(* Logix 5000 project; controller ZaxisVmpSample 1769-L16ER-BB1B rev 30.11; software revision 30.00 *)

TASK MainTask (continuous, watchdog 500 ms) : MainProgram, VMP_Interface

MODULES
   Local : 1769-L16ER-BB1B (PointIO 0, rev 30.11)
      Pump01 : ETHERNET-MODULE (Ethernet 192.168.1.131, rev 1.1, Output RPI 20 ms)
      Pump02 : ETHERNET-MODULE (Ethernet 192.168.1.132, rev 1.1, Output RPI 20 ms)
      Pump03 : ETHERNET-MODULE (Ethernet 192.168.1.133, rev 1.1, Output RPI 20 ms)
      Pump00 : ETHERNET-MODULE (Ethernet 192.168.1.130, rev 1.1, Output RPI 20 ms)
      Discrete_IO : Embedded (PointIO 1, rev 30.11, Output RPI 20 ms)
           Local:1:I.Data.0   // Green Push Btn
           Local:1:I.Data.1   // Red Push Btn
END_MODULES

TYPE VMP_Cfg :
STRUCT
   ReadyInterlock : BOOL;   // ReadyInterlock
   EthernetRunReady : BOOL;   // EthernetRunReady
   HoldOnFault : BOOL;   // HoldOnFault
   Spare1_3 : BOOL;   // Spare Bit
   Spare1_4 : BOOL;   // Spare Bit
   Spare1_5 : BOOL;   // Spare Bit
   Spare1_6 : BOOL;   // Spare Bit
   Spare1_7 : BOOL;   // Spare Bit
   DecPlaces : SINT;   // DecimalPlaces
   SpareByte1 : SINT;   // Spare data1
   SpareByte2 : SINT;   // Spare data1
END_STRUCT
END_TYPE

TYPE VMP_IN :
STRUCT
   Ready : BOOL;   // Ready to Run
   Running : BOOL;   // Running
   Abort : BOOL;   // Abort State
   Direction : BOOL;   // Direction CCW
   ContinuousRun : BOOL;   // Continuous Run
   MotorRunning : BOOL;   // Motors Running
   AtMaxShot : BOOL;   // AtMaxShot
   CmdAck : BOOL;   // PLC Cmd Ack
   Spare1_8 : BOOL;   // Spare Bit
   Spare1_9 : BOOL;   // Spare Bit
   Spare1_10 : BOOL;   // Spare Bit
   Spare1_11 : BOOL;   // Spare Bit
   Spare1_12 : BOOL;   // Spare Bit
   Spare1_13 : BOOL;   // Spare Bit
   Spare1_14 : BOOL;   // Spare Bit
   Spare1_15 : BOOL;   // Spare Bit
   Spare1_16 : BOOL;   // Spare Bit
   Spare1_17 : BOOL;   // Spare Bit
   Spare1_18 : BOOL;   // Spare Bit
   Spare1_19 : BOOL;   // Spare Bit
   Spare1_20 : BOOL;   // Spare Bit
   Spare1_21 : BOOL;   // Spare Bit
   Spare1_22 : BOOL;   // Spare Bit
   Spare1_23 : BOOL;   // Spare Bit
   Spare1_24 : BOOL;   // Spare Bit
   Spare1_25 : BOOL;   // Spare Bit
   Spare1_26 : BOOL;   // Spare Bit
   Spare1_27 : BOOL;   // Spare Bit
   Spare1_28 : BOOL;   // Spare Bit
   FaultDispenseMotor : BOOL;   // Disp Motor Fault
   FaultAdjustMotor : BOOL;   // Adj Motor Fault
   FaultAdjustSensor : BOOL;   // Adj Sensor Fault
   CurProgram : DINT;   // Program
   CurRevolutions : DINT;   // Revolutions
   CurVolume : REAL;   // Volume
   CurRpm : DINT;   // RPM
   VolumeDint : DINT;   // Vol as Dint
   Spare_In_DInt2 : DINT;   // Spare data2
   FineAdj : INT;   // FineAdj
   Spare_In_Int1 : INT;   // Spare_In_Int 1
END_STRUCT
END_TYPE

TYPE VMP_OUT :
STRUCT
   OkToRun : BOOL;   // Ok to Run
   Start : BOOL;   // Start
   Abort : BOOL;   // Abort Run
   Direction : BOOL;   // Direction CCW
   ContinuousRun : BOOL;   // Run Continuously
   SetMaxShotSize : BOOL;   // Set Max Volumn
   SetShotSize : BOOL;   // Set Volume
   IgnorePLC : BOOL;   // Ignore PLC Cmds
   IncFineAdj : BOOL;   // IncFineAdj
   DecFineAdj : BOOL;   // DecFineAdj
   ResetRevsCnt : BOOL;   // ResetRevsCnt
   Spare11 : BOOL;   // Spare11
   Spare12 : BOOL;   // Spare12
   Spare13 : BOOL;   // Spare13
   Spare14 : BOOL;   // Spare14
   Spare15 : BOOL;   // Spare15
   Spare16 : BOOL;   // Spare16
   Spare17 : BOOL;   // Spare17
   Spare18 : BOOL;   // Spare18
   Spare19 : BOOL;   // Spare19
   Spare20 : BOOL;   // Spare20
   Spare21 : BOOL;   // Spare21
   Spare22 : BOOL;   // Spare22
   Spare23 : BOOL;   // Spare23
   Spare24 : BOOL;   // Spare24
   Spare25 : BOOL;   // Spare25
   Spare26 : BOOL;   // Spare26
   Spare27 : BOOL;   // Spare27
   Spare28 : BOOL;   // Spare28
   Spare29 : BOOL;   // Spare29
   Spare30 : BOOL;   // Spare30
   Spare31 : BOOL;   // Spare31
   Program : DINT;   // Program
   Revolutions : DINT;   // Revolutions
   Volume : REAL;   // Volume
   Rpm : DINT;   // RPM
   Spare_Out_DInt1 : DINT;   // SpareDInt1
   Spare_Out_DInt2 : DINT;   // SpareDInt2
   FineAdjOut : INT;   // FineAdj
   Spare_Out_Int1 : INT;   // Sapre_Out_Int1
END_STRUCT
END_TYPE

TYPE VMP_Prg :
STRUCT
   CalDispenseTime : BOOL;   // CalDispenseTime
   Direction : BOOL;   // Direction CCW
   SetShotSize : BOOL;   // Set Volume
   ContinuousRun : BOOL;   // Run Continuously
   Spare1_4 : BOOL;   // Spare Bit
   Spare1_5 : BOOL;   // Spare Bit
   Spare1_6 : BOOL;   // Spare Bit
   Spare1_7 : BOOL;   // Spare Bit
   Spare1_8 : BOOL;   // Spare Bit
   Spare1_9 : BOOL;   // Spare Bit
   Spare1_10 : BOOL;   // Spare Bit
   Spare1_11 : BOOL;   // Spare Bit
   Spare1_12 : BOOL;   // Spare Bit
   Spare1_13 : BOOL;   // Spare Bit
   Spare1_14 : BOOL;   // Spare Bit
   Spare1_15 : BOOL;   // Spare Bit
   Spare1_16 : BOOL;   // Spare Bit
   Spare1_17 : BOOL;   // Spare Bit
   Spare1_18 : BOOL;   // Spare Bit
   Spare1_19 : BOOL;   // Spare Bit
   Spare1_20 : BOOL;   // Spare Bit
   Spare1_21 : BOOL;   // Spare Bit
   Spare1_22 : BOOL;   // Spare Bit
   Spare1_23 : BOOL;   // Spare Bit
   Spare1_24 : BOOL;   // Spare Bit
   Spare1_25 : BOOL;   // Spare Bit
   Spare1_26 : BOOL;   // Spare Bit
   Spare1_27 : BOOL;   // Spare Bit
   Spare1_28 : BOOL;   // Spare Bit
   Spare1_29 : BOOL;   // Spare Bit
   Spare1_30 : BOOL;   // Spare Bit
   Spare1_31 : BOOL;   // Spare Bit
   Program : DINT;   // Program
   PullBack : DINT;   // PullBack
   InitialRPM : DINT;   // InitialRPM
   RPM : DINT;   // RPM
   FinalRPM : DINT;   // FinalRPM
   FineAdjust : DINT;   // FineAdjust
   Acceleration : DINT;   // Acceleration
   Deceleration : DINT;   // Deceleration
   LoopCycles : DINT;   // LoopCycles
   LinkedProgram : DINT;   // LinkedProgram
   LinkedTimeDelay : DINT;   // LinkedTimeDelay
   MotorCurrent : DINT;   // MotorCurrent
   Revolutions : DINT;   // Revolutions
   AprxDispenseTime : DINT;   // DispenseTime
   Volume : REAL;   // Volume
   ProgramName : STRING;   // ProgramName
END_STRUCT
END_TYPE

TYPE VMP_Setup :
STRUCT
   ReadyInterlock : BOOL;   // RdyInputEnabled
   EthernetRunReady : BOOL;   // EthSendBusy
   HoldOnFault : BOOL;   // HoldOnFault
   Spare1_3 : BOOL;   // Spare Bit
   Spare1_4 : BOOL;   // Spare Bit
   Spare1_5 : BOOL;   // Spare Bit
   Spare1_6 : BOOL;   // Spare Bit
   Spare1_7 : BOOL;   // Spare Bit
   Spare1_8 : BOOL;   // Spare Bit
   Spare1_9 : BOOL;   // Spare Bit
   Spare1_10 : BOOL;   // Spare Bit
   Spare1_11 : BOOL;   // Spare Bit
   Spare1_12 : BOOL;   // Spare Bit
   Spare1_13 : BOOL;   // Spare Bit
   Spare1_14 : BOOL;   // Spare Bit
   Spare1_15 : BOOL;   // Spare Bit
   Spare1_16 : BOOL;   // Spare Bit
   Spare1_17 : BOOL;   // Spare Bit
   Spare1_18 : BOOL;   // Spare Bit
   Spare1_19 : BOOL;   // Spare Bit
   Spare1_20 : BOOL;   // Spare Bit
   Spare1_21 : BOOL;   // Spare Bit
   Spare1_22 : BOOL;   // Spare Bit
   Spare1_23 : BOOL;   // Spare Bit
   Spare1_24 : BOOL;   // Spare Bit
   Spare1_25 : BOOL;   // Spare Bit
   Spare1_26 : BOOL;   // Spare Bit
   Spare1_27 : BOOL;   // Spare Bit
   Spare1_28 : BOOL;   // Spare Bit
   Spare1_29 : BOOL;   // Spare Bit
   Spare1_30 : BOOL;   // Spare Bit
   Spare1_31 : BOOL;   // Spare Bit
   Baud : DINT;   // Baud
   PumpNumber : DINT;   // PumpNumber
   SpareDInt0 : DINT;   // SpareDInt0
   SpareDInt1 : DINT;   // SpareDInt1
   FirmwareRev : REAL;   // FirmRev
   Bore : REAL;   // Bore
   SpareReal0 : REAL;   // SpareReal0
   SpareReal1 : REAL;   // SpareReal1
   SerialNumber : STRING;   // SerialNumber
END_STRUCT
END_TYPE

TYPE VMP_TcpIP_Cfg :
STRUCT
   Status : DINT;   // Status
   Config_Capability : DINT;   // Capability
   Config_Control : DINT;   // IfCtrl
   Path_Size : INT;   // Epath
   Path : SINT[4];   // Padd
   IP_Address : DINT;   // IPAddr
   Network_Address : DINT;   // NetAddr
   Gateway_Address : DINT;   // GateWay
   Name_Server : DINT;   // DNS1
   Name_Server_2 : DINT;   // DNS2
   Domain_Name : STRING;   // Domain
   Host_Name : STRING;   // Host
   Safety_Network_Number : SINT[6];   // Ignore
   TTL : SINT;   // TTL
   Alloc_Control : SINT;   // MultCast
   Reserved : SINT;   // Reserved
   Num_Mcast : INT;   // MultCastAlloc
   Mcast_Start_Addr : DINT;   // MultCastStart
   Selected_Acd : BOOL;   // ACD
   Acd_Activity : SINT;   // ACDState
   Remote_MAC : SINT[6];   // MACRmt
   Arp_Pdu : SINT[28];   // ARP_PDU
   EthernetIP_Quick_Connect : BOOL;   // QuickCon
   Encp_Inactivity_Timeout : INT;   // InactTimeout
END_STRUCT
END_TYPE

PROGRAM MainProgram   (* main routine MainRoutine *)

ROUTINE MainRoutine   (* ladder *)
END_ROUTINE
END_PROGRAM

PROGRAM VMP_Interface   (* main routine PumpMainRoutine *)
VAR
   Debug : BOOL := 1;
   DispenseEnable : BOOL;
   DispenseRevolutions : DINT := 1;
   DispenseSetup : BOOL;
   DispenseSpeed : DINT := 200;
   DispenseVolume : REAL := 0.0111;
   DispenseVolumeDint : DINT := 111;
   DonotRun : BOOL;
   PmpIdx : ALIAS FOR PumpIdxCnt.ACC;
   PrimeRevolutions : DINT := 10;
   PrimeSpeed : DINT := 300;
   PumpIdxCnt : COUNTER := (PRE := 4);
   PumpIdxTimer : TIMER := (PRE := 100);
   PumpIn : VMP_IN[5];
   PumpOut : VMP_OUT[5] := ([0].OkToRun := 1, [0].Revolutions := 1, [0].Volume := 0.0111, [0].Rpm := 200, [1].OkToRun := 1, [1].Revolutions := 1, [1].Volume := 0.0111, [1].Rpm := 200, [2].OkToRun := 1, [2].Revolutions := 1, [2].Volume := 0.0111, [2].Rpm := 200, [3].OkToRun := 1, [3].Revolutions := 1, [3].Volume := 0.0111, [3].Rpm := 200);
   PumpPrimeEnable : BOOL;
   TestDispense : BOOL;
   TestPrime : BOOL;
   TestRun : BOOL;
   TestTimer : TIMER := (PRE := 12000);
   ToggleOnScan : BOOL;
END_VAR

ROUTINE PumpDispense   (* ladder *)
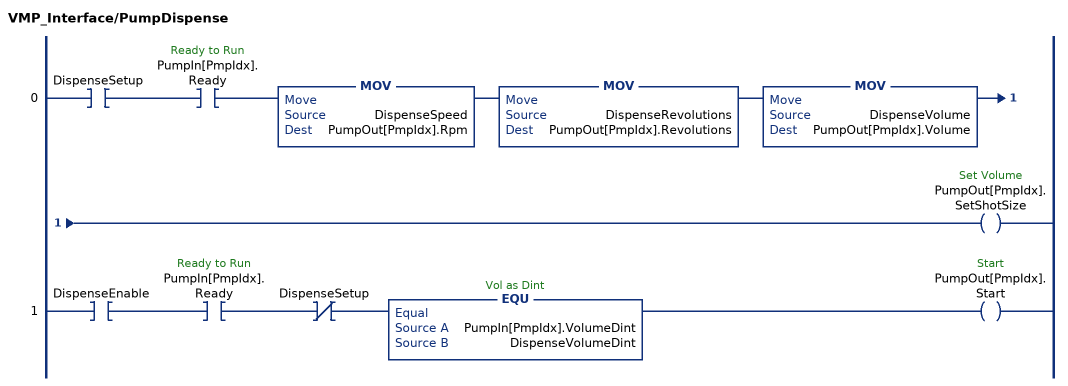
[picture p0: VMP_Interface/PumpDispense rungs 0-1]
   0: XIC(DispenseSetup)XIC(PumpIn[PmpIdx].Ready)MOV(DispenseSpeed,PumpOut[PmpIdx].Rpm)MOV(DispenseRevolutions,PumpOut[PmpIdx].Revolutions)MOV(DispenseVolume,PumpOut[PmpIdx].Volume)OTE(PumpOut[PmpIdx].SetShotSize);
   1: XIC(DispenseEnable)XIC(PumpIn[PmpIdx].Ready)XIO(DispenseSetup)EQU(PumpIn[PmpIdx].VolumeDint,DispenseVolumeDint)OTE(PumpOut[PmpIdx].Start);
END_ROUTINE

ROUTINE PumpMainRoutine   (* ladder *)
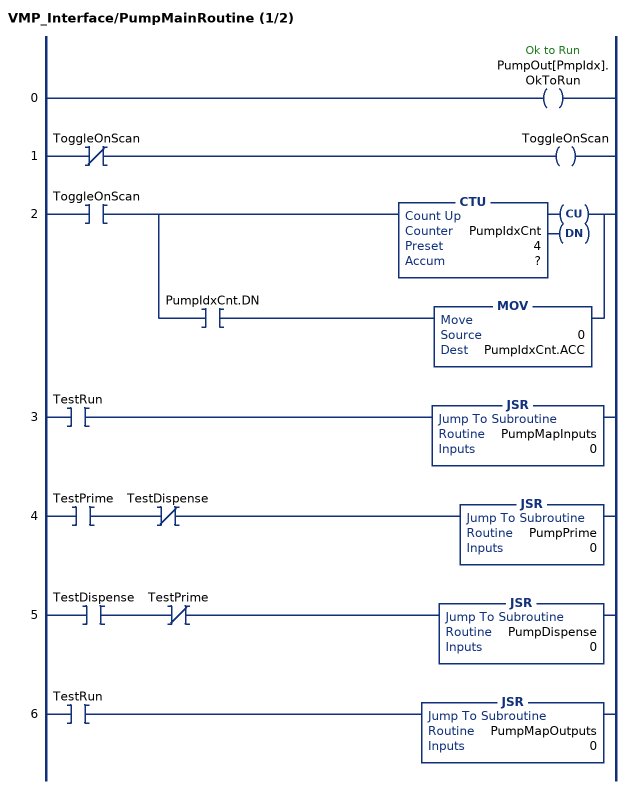
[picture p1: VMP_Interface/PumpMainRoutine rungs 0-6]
   0: OTE(PumpOut[PmpIdx].OkToRun);
   1: XIO(ToggleOnScan)OTE(ToggleOnScan);
   2: XIC(ToggleOnScan)[CTU(PumpIdxCnt,?,?) ,XIC(PumpIdxCnt.DN) MOV(0,PumpIdxCnt.ACC) ];
   3: XIC(TestRun)JSR(PumpMapInputs,0);
   4: XIC(TestPrime)XIO(TestDispense)JSR(PumpPrime,0);
   5: XIC(TestDispense)XIO(TestPrime)JSR(PumpDispense,0);
   6: XIC(TestRun)JSR(PumpMapOutputs,0);
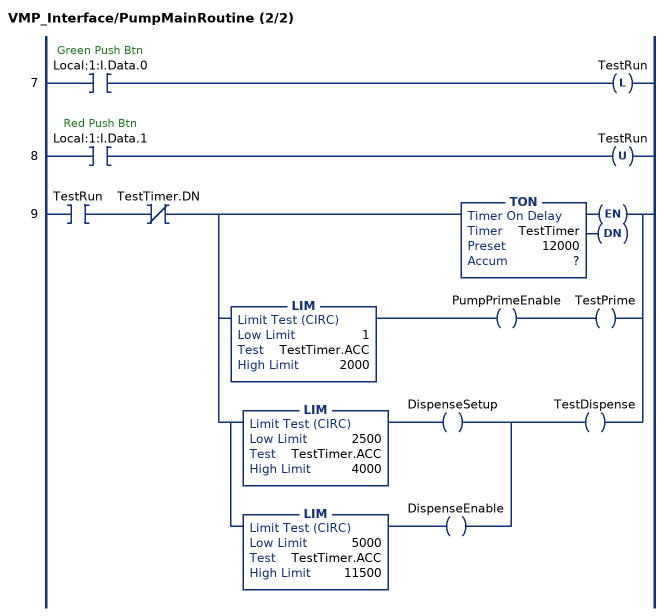
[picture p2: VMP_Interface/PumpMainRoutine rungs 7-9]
   7: XIC(Local:1:I.Data.0)OTL(TestRun);
   8: XIC(Local:1:I.Data.1)OTU(TestRun);
   9: XIC(TestRun)XIO(TestTimer.DN)[TON(TestTimer,?,?) ,LIM(1,TestTimer.ACC,2000) OTE(PumpPrimeEnable) OTE(TestPrime) ,[LIM(2500,TestTimer.ACC,4000) OTE(DispenseSetup) ,LIM(5000,TestTimer.ACC,11500) OTE(DispenseEnable) ] OTE(TestDispense) ];
END_ROUTINE

ROUTINE PumpMapInputs   (* ladder *)
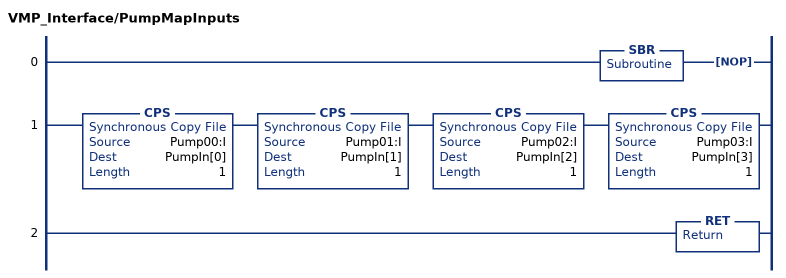
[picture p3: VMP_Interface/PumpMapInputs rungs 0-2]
   0: SBR()NOP();
   1: CPS(Pump00:I,PumpIn[0],1)CPS(Pump01:I,PumpIn[1],1)CPS(Pump02:I,PumpIn[2],1)CPS(Pump03:I,PumpIn[3],1);
   2: RET();
END_ROUTINE

ROUTINE PumpMapOutputs   (* ladder *)
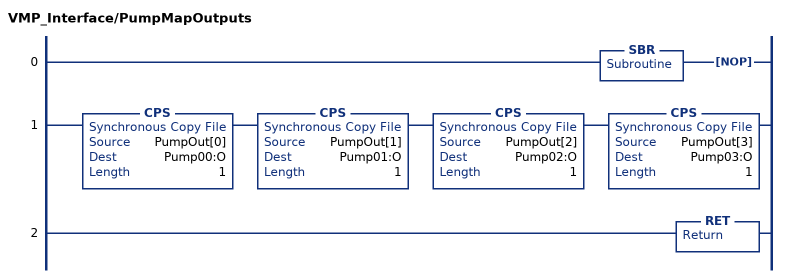
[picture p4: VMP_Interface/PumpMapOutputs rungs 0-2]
   0: SBR()NOP();
   1: CPS(PumpOut[0],Pump00:O,1)CPS(PumpOut[1],Pump01:O,1)CPS(PumpOut[2],Pump02:O,1)CPS(PumpOut[3],Pump03:O,1);
   2: RET();
END_ROUTINE

ROUTINE PumpPrime   (* ladder *)
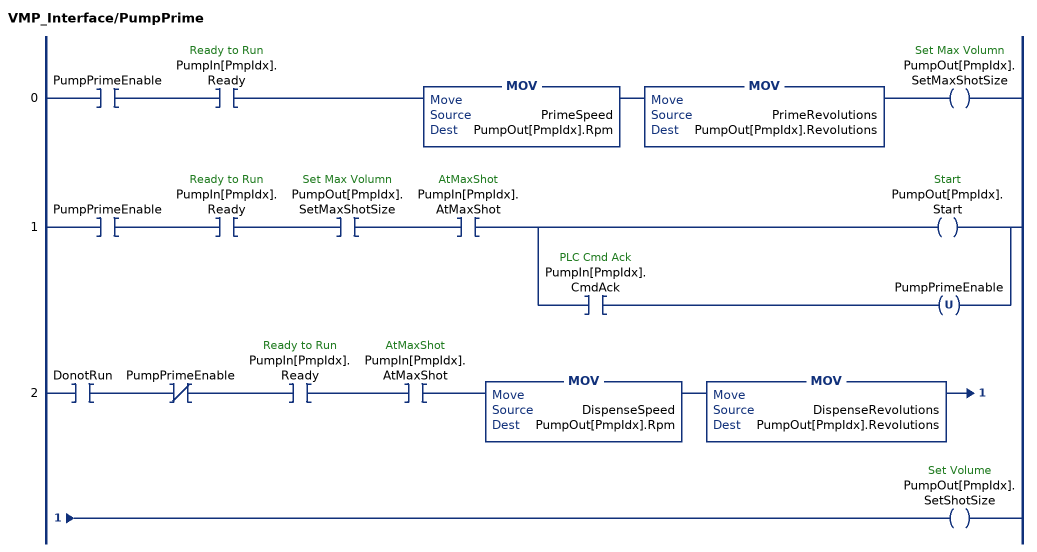
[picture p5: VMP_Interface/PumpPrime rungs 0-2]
   0: XIC(PumpPrimeEnable)XIC(PumpIn[PmpIdx].Ready)MOV(PrimeSpeed,PumpOut[PmpIdx].Rpm)MOV(PrimeRevolutions,PumpOut[PmpIdx].Revolutions)OTE(PumpOut[PmpIdx].SetMaxShotSize);
   1: XIC(PumpPrimeEnable)XIC(PumpIn[PmpIdx].Ready)XIC(PumpOut[PmpIdx].SetMaxShotSize)XIC(PumpIn[PmpIdx].AtMaxShot)[OTE(PumpOut[PmpIdx].Start) ,XIC(PumpIn[PmpIdx].CmdAck) OTU(PumpPrimeEnable) ];
   2: XIC(DonotRun)XIO(PumpPrimeEnable)XIC(PumpIn[PmpIdx].Ready)XIC(PumpIn[PmpIdx].AtMaxShot)MOV(DispenseSpeed,PumpOut[PmpIdx].Rpm)MOV(DispenseRevolutions,PumpOut[PmpIdx].Revolutions)OTE(PumpOut[PmpIdx].SetShotSize);
END_ROUTINE
END_PROGRAM
